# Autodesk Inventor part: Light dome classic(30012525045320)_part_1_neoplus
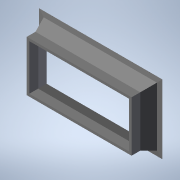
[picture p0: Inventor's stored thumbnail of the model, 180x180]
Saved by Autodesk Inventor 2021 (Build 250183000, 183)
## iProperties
Created: 2026-04
Part Number: Light dome classic(30012525045320)_part_1_neoplus
Material: Generic
Catalog Web Link: www.3dfindit.com
Description: Light dome classic_part_1_neoplus-
Vendor: KINGSPAN
Document SubType Name: Modeling
Designer: psAdmin
Manufacturer: KINGSPAN
Mass: 215474 g
Surface Area: 100954 cm^2
Volume: 215474 cm^3
Density: 1 g/cm^3
Appearance: PSOLRGB-255-255-255
Category: PARTsolutions
Company: KINGSPAN
Title: Light dome classic(30012525045320)_part_1_neoplus
Author: Cadenas PARTsolutions
PSOL_IDENT_0: {$CADENAS_DATA/23d-libs/kingspan_kla/light_dome_classic_neoplus/parts/part_1.prj},297 {VTYP=3D},{NB=
PSOL_IDENT_1: Light dome classic(30012525045320)_part_1_neoplus},{LINA=Light dome classic(30012525045320)_part_1_n
PSOL_IDENT_2: eoplus},{NN=Light dome classic_part_1_neoplus},{DATE=20.03.2025 09:30:52},{GEOMDATE=03.07.2024 07:48
PSOL_IDENT_3: :00},{VERSION=},{LINEID=10},{WBVAR=LODLEVEL,L,W,DP,OP,BA,INS,RT},{WBNUMERIC=W,RT}  {NB=Light dome cl
PSOL_IDENT_4: assic(30012525045320)_part_1_neoplus},{LINA=Light dome classic(30012525045320)_part_1_neoplus},{KT=D
PSOL_IDENT_5: UMMY},{IDNR=},{PN=Light dome classic},{LODLEVEL=300},{L=125},{W=250},{DRIVE=1},{WX=125,250,300},{DP=
PSOL_IDENT_6: 4},{OP=5},{BA=3},{INS=2},{INSX='2','without insulation'},{OPX='5','Pneumatic - NRWG F.6 LK'},{LX=125
PSOL_IDENT_7: 0},{XWX=2500},{HEI=1214.941},{BAX='1', 'PVC base 15 cm','2', 'PVC base 30 cm', '3', 'PVC base 50 cm'
PSOL_IDENT_8: , '4', 'Metal base single skin (steel), 30 cm', '5' , 'Metal base single skin (steel), 40 cm', '6'
PSOL_IDENT_9: , 'Metal base single skin (steel), 50 cm', '7' , 'Metal base double skin (aluminum), 30 cm', '8' , '
PSOL_IDENT_10: Metal base double skin (aluminum), 40 cm', '9' , 'Metal base double skin (aluminum), 50 cm', '10', '
PSOL_IDENT_11: Steel base 30 cm', '11' , 'Steel base 40 cm', '12', 'Steel base 50 cm', '13' , 'AK30 AL/AL', '14' , '
PSOL_IDENT_12: AK40 AL/AL', '15' , 'AK50 AL/AL', '16' , 'AK50 ST-TG'},{RT=0}
NB: Light dome classic(30012525045320)_part_1_neoplus
NN: Light dome classic_part_1_neoplus
NBSYN: $PN.($LODLEVEL.$L.$W.$DP.$OP.$BA.$INS.$RT.)_part_1_neoplus
LINA: Light dome classic(30012525045320)_part_1_neoplus
CATALOG: Light + Air
PN: Light dome classic
LODLEVEL: 300
L: 125
W: 250
DP: NSHE
OP: Pneumatic - NRWG F.6 LK
BA: PVC base 50 cm
INS: without insulation
RT: 0
SUPPLIER: KINGSPAN
ARTICLENO: Light dome classic(30012525045320)_part_1_neoplus
BOMINFO: Light dome classic(30012525045320)_part_1_neoplus
CREATOR: CADENAS GmbH
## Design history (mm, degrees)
sketch "Sketch_1"
  geometry: L1 (-1150.529, 500)-(-1207.495, 500); L2 (-1207.495, 500)-(-1207.495, 300); L3 (-1207.495, 300)-(-1305.041, 12.062); L4 (-1305.041, 12.062)-(-1420.088, 1.996); L5 (-1420.001, 0)-(-1250, 0); L6 (-1250, 0)-(-1150.529, 293.622); L7 (-1150.529, 293.622)-(-1150.529, 500); A1 r 1 centre (-1420.001, 1) between (-1420.088, 1.996) and (-1420.001, 0)
  constraints: 14 end point, 2 point on circle, 1 centre point
extrude "Extrusion1" join sketch "Sketch_1" stored distance "d0" = 2500; taper "d1" = 0 deg
sketch "Sketch_2"
  geometry: L1 (525.529, 500)-(525.529, 293.622); L2 (525.529, 293.622)-(625, 0); L3 (625, 0)-(795.001, 0); L4 (795.088, 1.996)-(680.041, 12.062); L5 (680.041, 12.062)-(582.495, 300); L6 (582.495, 300)-(582.495, 500); L7 (582.495, 500)-(525.529, 500); A1 r 1 centre (795.001, 1) between (795.001, 0) and (795.088, 1.996)
  constraints: 14 end point, 2 point on circle, 1 centre point
extrude "Extrusion2" join sketch "Sketch_2" stored distance "d2" = 5000; taper "d3" = 0 deg
sketch "Sketch_3"
  geometry: L1 (1420.088, 1.996)-(1305.041, 12.062); L2 (1305.041, 12.062)-(1207.495, 300); L3 (1207.495, 300)-(1207.495, 500); L4 (1207.495, 500)-(1150.529, 500); L5 (1150.529, 500)-(1150.529, 293.622); L6 (1150.529, 293.622)-(1250, 0); L7 (1250, 0)-(1420.001, 0); A1 r 1 centre (1420.001, 1) between (1420.001, 0) and (1420.088, 1.996)
  constraints: 14 end point, 2 point on circle, 1 centre point
extrude "Extrusion3" join sketch "Sketch_3" stored distance "d4" = 2500; taper "d5" = 0 deg
sketch "Sketch_4"
  geometry: L1 (-525.529, 500)-(-582.495, 500); L2 (-582.495, 500)-(-582.495, 300); L3 (-582.495, 300)-(-680.041, 12.062); L4 (-680.041, 12.062)-(-795.088, 1.996); L5 (-795.001, 0)-(-625, 0); L6 (-625, 0)-(-525.529, 293.622); L7 (-525.529, 293.622)-(-525.529, 500); A1 r 1 centre (-795.001, 1) between (-795.088, 1.996) and (-795.001, 0)
  constraints: 14 end point, 2 point on circle, 1 centre point
extrude "Extrusion4" join sketch "Sketch_4" stored distance "d6" = 5000; taper "d7" = 0 deg
sketch "Sketch_5"
  geometry: L1 (-1150, 600)-(-2500, 600); L2 (-2500, 600)-(-2500, -30); L3 (-2500, -30)-(-1319.29, -30); L4 (-1319.29, -30)-(-1309.127, 0); L5 (-1309.127, 0)-(-1420.001, 0); L6 (-1420.088, 1.996)-(-1305.041, 12.062); L7 (-1305.041, 12.062)-(-1207.495, 300); L8 (-1207.495, 300)-(-1207.495, 500); L9 (-1207.495, 500)-(-1150, 500); L10 (-1150, 500)-(-1150, 600); A1 r 1 centre (-1420.001, 1) between (-1420.088, 1.996) and (-1420.001, 0)
  constraints: 20 end point, 2 point on circle, 1 centre point
extrude "Extrusion5" cut sketch "Sketch_5" stored distance "d8" = 2500; taper "d9" = 0 deg
sketch "Sketch_6"
  geometry: L1 (2500, -30)-(2500, 600); L2 (2500, 600)-(1150, 600); L3 (1150, 600)-(1150, 500); L4 (1150, 500)-(1207.495, 500); L5 (1207.495, 500)-(1207.495, 300); L6 (1207.495, 300)-(1305.041, 12.062); L7 (1305.041, 12.062)-(1420.088, 1.996); L8 (1420.001, 0)-(1309.127, 0); L9 (1309.127, 0)-(1319.29, -30); L10 (1319.29, -30)-(2500, -30); A1 r 1 centre (1420.001, 1) between (1420.001, 0) and (1420.088, 1.996)
  constraints: 20 end point, 2 point on circle, 1 centre point
extrude "Extrusion6" cut sketch "Sketch_6" stored distance "d10" = 2500; taper "d11" = 0 deg
sketch "Sketch_7"
  geometry: L1 (1250, 600)-(525, 600); L2 (525, 600)-(525, 500); L3 (525, 500)-(582.495, 500); L4 (582.495, 500)-(582.495, 300); L5 (582.495, 300)-(680.041, 12.062); L6 (680.041, 12.062)-(795.088, 1.996); L7 (795.001, 0)-(684.127, 0); L8 (684.127, 0)-(694.29, -30); L9 (694.29, -30)-(1250, -30); L10 (1250, -30)-(1250, 600); A1 r 1 centre (795.001, 1) between (795.001, 0) and (795.088, 1.996)
  constraints: 20 end point, 2 point on circle, 1 centre point
extrude "Extrusion7" cut sketch "Sketch_7" stored distance "d12" = 5000; taper "d13" = 0 deg
sketch "Sketch_9"
  geometry: L1 (-1250, 600)-(-1250, -30); L2 (-1250, -30)-(-694.29, -30); L3 (-694.29, -30)-(-684.127, 0); L4 (-684.127, 0)-(-795.001, 0); L5 (-795.088, 1.996)-(-680.041, 12.062); L6 (-680.041, 12.062)-(-582.495, 300); L7 (-582.495, 300)-(-582.495, 500); L8 (-582.495, 500)-(-525, 500); L9 (-525, 500)-(-525, 600); L10 (-525, 600)-(-1250, 600); A1 r 1 centre (-795.001, 1) between (-795.088, 1.996) and (-795.001, 0)
  constraints: 20 end point, 2 point on circle, 1 centre point
extrude "Extrusion8" cut sketch "Sketch_9" stored distance "d14" = 5000; taper "d15" = 0 deg
node "1_XY"
node "1_YZ"
node "1_ZX"
node "1_X"
node "1_Y"
node "1_Z"
node "1_Center"
node "IP_for_dummy_XY"
node "IP_for_dummy_YZ"
node "IP_for_dummy_ZX"
node "IP_for_dummy_X"
node "IP_for_dummy_Y"
node "IP_for_dummy_Z"
node "IP_for_dummy_Center"
node "IP_for_part_10_1_XY"
node "IP_for_part_10_1_YZ"
node "IP_for_part_10_1_ZX"
node "IP_for_part_10_1_X"
node "IP_for_part_10_1_Y"
node "IP_for_part_10_1_Z"
node "IP_for_part_10_1_Center"
node "IP_for_part_2_XY"
node "IP_for_part_2_YZ"
node "IP_for_part_2_ZX"
node "IP_for_part_2_X"
node "IP_for_part_2_Y"
node "IP_for_part_2_Z"
node "IP_for_part_2_Center"
node "light_dome_classic_XY"
node "light_dome_classic_YZ"
node "light_dome_classic_ZX"
node "light_dome_classic_X"
node "light_dome_classic_Y"
node "light_dome_classic_Z"
node "light_dome_classic_Center"
body "Solid1"
other parameters: "d16" = 0, "d17" = 0, "d18" = 0, "d19" = 0
